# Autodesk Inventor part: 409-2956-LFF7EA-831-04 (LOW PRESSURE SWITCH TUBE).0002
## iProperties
Created: 2011-01
Material: 3/8" OD TUBE - SS
Document SubType Name: Modeling
Designer: S. Boerckel
Engineer: Steve Boerckel
Mass: 199.016 g
Surface Area: 326.016 cm^2
Volume: 24.784 cm^3
Density: 8.03 g/cm^3
User Status: CUT/BEND
Description: PRESSURE SWITCH LOW TUBE
LGTH: 25.472 in
Author: S. Boerckel
Revision Number: 0
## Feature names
1. Sweep1
